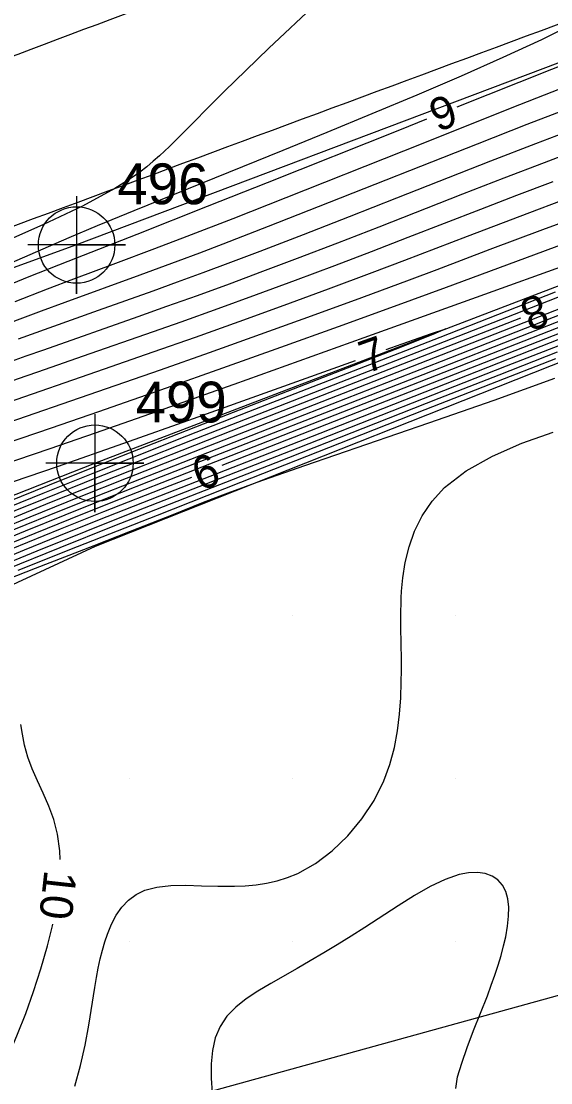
# Model space of a CAD drawing. Extents: x 2602990 to 2605851, y 618069 to 619180.
# Drawn here: x 2603243.4 to 2603275.8, y 618321.3 to 618386.4 of the extents above; entities that cross this region are included whole.
import ezdxf

# ---------------------------------------------------------------- set-up
doc = ezdxf.new("R2010")
doc.units = 0
for name, color, linetype in [('DTM Contours Major', 7, 'Continuous'), ('DTM Contours Minor', 7, 'Continuous'), ('DTM Contours Minor Text', 7, 'Continuous'), ('Exist DTM Breakline', 7, 'Continuous'), ('Exist DTM Breakline Cogo Number', 7, 'Continuous'), ('Exist DTM Breakline Cogo Point CELL', 7, 'Continuous'), ('Exist DTM Crownline', 7, 'Continuous'), ('Exist DTM Drainline', 7, 'Continuous'), ('Exist DTM Drainline Cogo Number', 7, 'Continuous'), ('Exist DTM Drainline Cogo Point CELL', 7, 'Continuous'), ('Exist DTM QL2 LIDAR Elevation Point', 7, 'Continuous'), ('Exist Roads EOP', 7, 'Continuous'), ('PH Exist DTM Breakline', 7, 'Continuous'), ('PH Exist DTM Obscure Area', 7, 'Continuous')]:
    doc.layers.add(name, color=color, linetype=linetype)

# ---------------------------------------------------------------- blocks, each defined once
blk = doc.blocks.new('EXIST DTM BREAKLINE COGO POINT')
at = {"layer": 'Exist DTM Breakline Cogo Point CELL'}
blk.add_lwpolyline([(0, 0.06), (0, -0.06), (0, 0), (0.06, 0), (-0.06, 0)], dxfattribs=at)
blk.add_circle((0, 0), 0.0469, dxfattribs=at)
blk = doc.blocks.new('EXIST DTM DRAINLINE COGO POINT')
at = {"layer": 'Exist DTM Drainline Cogo Point CELL'}
blk.add_lwpolyline([(0, 0.06), (0, -0.06), (0, 0), (0.06, 0), (-0.06, 0)], dxfattribs=at)
blk.add_circle((0, 0), 0.0469, dxfattribs=at)

msp = doc.modelspace()

# ---------------------------------------------------------------- linework, layer by layer
at = {"layer": 'DTM Contours Major'}
for points in [[(2603232.042, 618350.596), (2603232.796, 618350.941), (2603234.02, 618351.488), (2603235.249, 618352.027), (2603236.484, 618352.559), (2603237.724, 618353.086), (2603240.316, 618354.172), (2603243.023, 618355.288), (2603245.739, 618356.391), (2603248.557, 618357.518), (2603251.681, 618358.75), (2603259.068, 618361.639), (2603269.134, 618365.569), (2603283.544, 618371.218), (2603285.941, 618372.151), (2603288.321, 618373.072), (2603290.658, 618373.969), (2603292.932, 618374.831), (2603294.547, 618375.436), (2603297.726, 618376.612), (2603305.437, 618379.437), (2603325.265, 618386.744)], [(2603275.946, 618376.566), (2603273.731, 618375.723), (2603271.513, 618374.867), (2603267.062, 618373.138), (2603264.824, 618372.273), (2603262.574, 618371.415), (2603260.163, 618370.511), (2603257.768, 618369.629), (2603255.419, 618368.776), (2603253.148, 618367.963), (2603250.987, 618367.198), (2603247.571, 618366.005), (2603244.375, 618364.896), (2603243.115, 618364.454), (2603241.834, 618363.997), (2603240.512, 618363.517), (2603239.134, 618363.003), (2603237.103, 618362.225), (2603234.953, 618361.384), (2603230.386, 618359.589), (2603228.019, 618358.671), (2603225.675, 618357.78)]]:
    msp.add_lwpolyline(points, dxfattribs=at)
at = {"layer": 'DTM Contours Minor'}
for points in [[(2603324.577, 618403.317), (2603322.127, 618402.396), (2603318.389, 618401.013), (2603317.044, 618400.508), (2603315.774, 618400.025), (2603314.571, 618399.561), (2603313.423, 618399.112), (2603312.32, 618398.675), (2603310.615, 618397.984), (2603308.924, 618397.283), (2603307.17, 618396.544), (2603304.397, 618395.361), (2603295.959, 618391.738), (2603291.729, 618389.935), (2603289.635, 618389.049), (2603287.605, 618388.196), (2603285.68, 618387.395), (2603284.13, 618386.757), (2603282.641, 618386.15), (2603279.672, 618384.956), (2603270.072, 618381.131)], [(2603230.899, 618351.261), (2603232.523, 618351.981), (2603234.797, 618352.972), (2603236.387, 618353.653), (2603237.889, 618354.288), (2603239.501, 618354.962), (2603241.21, 618355.669), (2603243.003, 618356.405), (2603244.868, 618357.163), (2603248.004, 618358.424), (2603250.561, 618359.439), (2603253.762, 618360.7), (2603260.83, 618363.464), (2603273.604, 618368.443), (2603287.265, 618373.796), (2603290.393, 618375.014), (2603293.467, 618376.203), (2603297.403, 618377.709), (2603300.32, 618378.809), (2603305.717, 618380.822), (2603313.054, 618383.538), (2603329.838, 618389.732)], [(2603261.504, 618387.535), (2603258.551, 618384.748), (2603257.131, 618383.391), (2603255.828, 618382.119), (2603255.057, 618381.347), (2603253.687, 618379.95), (2603253.059, 618379.318), (2603252.451, 618378.723), (2603251.848, 618378.162), (2603251.461, 618377.82), (2603251.06, 618377.486), (2603250.634, 618377.156), (2603250.174, 618376.824), (2603249.668, 618376.489), (2603249.106, 618376.144), (2603247.123, 618375.074), (2603244.699, 618373.921), (2603241.954, 618372.712)], [(2603277.305, 618386.282), (2603275.256, 618385.263), (2603272.901, 618384.172), (2603270.327, 618383.036), (2603267.62, 618381.879), (2603264.866, 618380.727), (2603262.092, 618379.582), (2603259.4, 618378.482), (2603250.263, 618374.78), (2603248.017, 618373.853), (2603246.286, 618373.122), (2603243.894, 618372.089), (2603240.538, 618370.626)], [(2603255.688, 618359.187), (2603263.04, 618362.061), (2603279.19, 618368.395), (2603282.779, 618369.794), (2603284.501, 618370.46), (2603286.202, 618371.112), (2603287.902, 618371.757), (2603289.622, 618372.402), (2603291.762, 618373.195), (2603293.952, 618373.996), (2603302.985, 618377.265), (2603307.387, 618378.871), (2603325.442, 618385.504)], [(2603238.982, 618351.734), (2603239.621, 618352.003), (2603241.64, 618352.839), (2603244.34, 618353.944), (2603247.34, 618355.154), (2603250.445, 618356.384), (2603260.34, 618360.258), (2603273.119, 618365.279), (2603276.379, 618366.555), (2603280.836, 618368.288), (2603283.497, 618369.311), (2603286.09, 618370.291), (2603287.416, 618370.786), (2603289.927, 618371.711), (2603292.552, 618372.665), (2603297.95, 618374.609), (2603303.224, 618376.505), (2603308.514, 618378.427), (2603321.931, 618383.339), (2603327.334, 618385.332)], [(2603279.496, 618383.471), (2603273.91, 618381.27), (2603266.799, 618378.447), (2603259.591, 618375.584), (2603256.333, 618374.299), (2603253.51, 618373.199), (2603251.536, 618372.444), (2603249.137, 618371.547), (2603246.582, 618370.596), (2603244.96, 618369.98), (2603242.977, 618369.207)], [(2603278.586, 618381.696), (2603274.359, 618380.063), (2603271.308, 618378.867), (2603261.577, 618375.019), (2603258.513, 618373.816), (2603255.727, 618372.737), (2603254.294, 618372.191), (2603252.976, 618371.696), (2603250.634, 618370.833), (2603246.036, 618369.17), (2603244.593, 618368.636), (2603242.953, 618368.014), (2603242.033, 618367.658), (2603239.439, 618366.634), (2603229.996, 618362.845), (2603226.732, 618361.55), (2603223.628, 618360.343), (2603221.906, 618359.689), (2603220.263, 618359.076), (2603218.677, 618358.493), (2603217.297, 618357.991)], [(2603268.214, 618380.39), (2603266.551, 618379.727), (2603258.435, 618376.492), (2603254.775, 618375.038), (2603250.453, 618373.333), (2603246.232, 618371.683), (2603243.838, 618370.73), (2603240.938, 618369.559), (2603233.675, 618366.612), (2603229.728, 618365.015), (2603225.849, 618363.457), (2603222.246, 618362.028), (2603219.869, 618361.1), (2603215.419, 618359.389), (2603207.46, 618356.337), (2603204.769, 618355.31), (2603202.133, 618354.311), (2603197.891, 618352.72), (2603196.251, 618352.098), (2603194.676, 618351.476), (2603193.162, 618350.839), (2603191.704, 618350.169), (2603190.299, 618349.451), (2603188.941, 618348.673)], [(2603276.602, 618379.55), (2603274.89, 618378.895), (2603272.142, 618377.829), (2603266.365, 618375.557), (2603263.467, 618374.417), (2603260.654, 618373.316), (2603257.989, 618372.289), (2603256.195, 618371.61), (2603254.508, 618370.981), (2603252.924, 618370.4), (2603251.439, 618369.863), (2603248.081, 618368.667), (2603245.055, 618367.591), (2603243.19, 618366.908)], [(2603277.384, 618378.473), (2603275.422, 618377.731), (2603272.943, 618376.779), (2603270.41, 618375.793), (2603265.29, 618373.787), (2603262.757, 618372.802), (2603260.277, 618371.85), (2603258.158, 618371.052), (2603256.112, 618370.295), (2603254.149, 618369.579), (2603252.282, 618368.908), (2603250.519, 618368.281), (2603244.728, 618366.249), (2603243.647, 618365.864), (2603242.526, 618365.458)], [(2603276.469, 618375.402), (2603274.521, 618374.668), (2603270.705, 618373.207), (2603266.856, 618371.731), (2603264.867, 618370.977), (2603262.193, 618369.981), (2603259.456, 618368.977), (2603256.715, 618367.986), (2603254.025, 618367.024), (2603251.444, 618366.112), (2603247.982, 618364.905), (2603242.563, 618363.034)], [(2603276.988, 618374.236), (2603275.32, 618373.616), (2603272.1, 618372.402), (2603268.852, 618371.173), (2603267.148, 618370.534), (2603264.223, 618369.452), (2603261.148, 618368.329), (2603258.009, 618367.197), (2603254.889, 618366.084), (2603251.875, 618365.019), (2603248.044, 618363.683), (2603242.004, 618361.609)], [(2603277.464, 618373.057), (2603274.778, 618372.07), (2603269.423, 618370.086), (2603266.226, 618368.914), (2603262.799, 618367.671), (2603259.254, 618366.395), (2603255.701, 618365.127), (2603252.251, 618363.907), (2603248.097, 618362.458), (2603245.196, 618361.462), (2603241.459, 618360.187)], [(2603276.657, 618371.416), (2603271.775, 618369.658), (2603264.366, 618366.987), (2603260.389, 618365.56), (2603256.4, 618364.136), (2603252.525, 618362.764), (2603247.893, 618361.145), (2603245.13, 618360.195), (2603239.035, 618358.121)], [(2603240.938, 618354.805), (2603243.907, 618356.024), (2603246.945, 618357.251), (2603249.812, 618358.391), (2603253.938, 618360.013), (2603271.955, 618367.048), (2603283.767, 618371.679)], [(2603241.137, 618354.141), (2603243.629, 618355.163), (2603246.066, 618356.149), (2603248.768, 618357.226), (2603251.969, 618358.486), (2603268, 618364.751), (2603281.124, 618369.898)], [(2603242.64, 618356.632), (2603244.704, 618357.472), (2603247.878, 618358.748), (2603249.988, 618359.588), (2603253.512, 618360.979), (2603257.314, 618362.47), (2603269.043, 618367.042), (2603276.129, 618369.808)], [(2603241.955, 618354.103), (2603244.225, 618355.031), (2603246.397, 618355.907), (2603248.986, 618356.937), (2603253.987, 618358.899), (2603264.4, 618362.967), (2603281.079, 618369.507)], [(2603241.8, 618355.537), (2603243.44, 618356.209), (2603245.122, 618356.892), (2603248.168, 618358.114), (2603250.998, 618359.235), (2603257.009, 618361.593), (2603272.791, 618367.75), (2603274, 618368.224)], [(2603265.745, 618366.285), (2603266.032, 618366.387), (2603268.458, 618367.242), (2603269.401, 618367.544), (2603268.59, 618367.192), (2603266.291, 618366.283), (2603254.511, 618361.701), (2603249.508, 618359.736), (2603247.981, 618359.13), (2603245.089, 618357.969), (2603242.511, 618356.919)], [(2603240.86, 618352.88), (2603243.57, 618353.999), (2603246.222, 618355.079), (2603248.64, 618356.047), (2603251.863, 618357.316), (2603261.685, 618361.158), (2603276.497, 618366.971)], [(2603242.416, 618352.8), (2603245.76, 618354.151), (2603249.004, 618355.441), (2603258.998, 618359.36), (2603268.99, 618363.294), (2603272.659, 618364.733), (2603276.239, 618366.132)], [(2603242.896, 618358.193), (2603245.582, 618359.117), (2603249.653, 618360.539), (2603253.935, 618362.058), (2603263.862, 618365.611)], [(2603243.185, 618352.763), (2603246.816, 618354.207), (2603251.718, 618356.13), (2603256.833, 618358.139), (2603264.249, 618361.068), (2603268.125, 618362.595), (2603272.149, 618364.172), (2603276.15, 618365.728)], [(2603241.458, 618351.802), (2603244.245, 618352.882), (2603247.832, 618354.267), (2603250.072, 618355.14), (2603252.687, 618356.175), (2603254.438, 618356.873), (2603255.557, 618357.306), (2603256.21, 618357.551), (2603256.959, 618357.826), (2603257.827, 618358.138), (2603260.757, 618359.163), (2603268.348, 618361.78), (2603272.358, 618363.184), (2603276.074, 618364.523)], [(2603246.647, 618321.116), (2603247.007, 618322.38), (2603247.287, 618323.635), (2603247.51, 618324.863), (2603247.875, 618327.169), (2603247.979, 618327.78), (2603248.09, 618328.364), (2603248.21, 618328.923), (2603248.342, 618329.455), (2603248.487, 618329.961), (2603248.65, 618330.442), (2603248.902, 618331.053), (2603249.198, 618331.61), (2603249.543, 618332.104), (2603249.943, 618332.527), (2603250.407, 618332.873), (2603250.939, 618333.132), (2603251.691, 618333.329), (2603252.536, 618333.419), (2603253.455, 618333.435), (2603254.426, 618333.41), (2603255.428, 618333.379), (2603256.441, 618333.374), (2603257.104, 618333.402), (2603257.761, 618333.463), (2603258.413, 618333.562), (2603259.058, 618333.707), (2603259.695, 618333.904), (2603260.324, 618334.16), (2603261.407, 618334.762), (2603262.438, 618335.539), (2603263.395, 618336.462), (2603264.254, 618337.504), (2603264.994, 618338.636), (2603265.592, 618339.83), (2603265.967, 618340.845), (2603266.244, 618341.873), (2603266.438, 618342.903), (2603266.564, 618343.926), (2603266.636, 618344.931), (2603266.668, 618345.907), (2603266.675, 618346.602), (2603266.673, 618347.278), (2603266.645, 618349.231), (2603266.642, 618349.866), (2603266.644, 618350.263), (2603266.651, 618350.661), (2603266.666, 618351.059), (2603266.688, 618351.461), (2603266.72, 618351.865), (2603266.763, 618352.275), (2603266.912, 618353.227), (2603267.146, 618354.191), (2603267.484, 618355.151), (2603267.946, 618356.087), (2603268.55, 618356.982), (2603269.315, 618357.818), (2603270.647, 618358.849), (2603272.25, 618359.75), (2603274.052, 618360.535), (2603275.982, 618361.222)], [(2603242.766, 618354.058), (2603245.778, 618355.282), (2603248.43, 618356.342), (2603252.488, 618357.936), (2603253.825, 618358.459)], [(2603245.75, 618335.011), (2603245.738, 618335.548), (2603245.598, 618336.575), (2603245.367, 618337.459), (2603245.063, 618338.294), (2603244.718, 618339.086), (2603244.367, 618339.844), (2603244.041, 618340.573), (2603243.774, 618341.283), (2603243.577, 618342.017), (2603243.449, 618342.701), (2603243.354, 618343.3)], [(2603270, 618320.984), (2603270.122, 618321.689), (2603270.368, 618322.538), (2603270.705, 618323.495), (2603271.101, 618324.525), (2603271.525, 618325.594), (2603271.943, 618326.666), (2603272.181, 618327.307), (2603272.403, 618327.934), (2603272.606, 618328.546), (2603272.786, 618329.142), (2603272.941, 618329.719), (2603273.068, 618330.276), (2603273.182, 618330.927), (2603273.244, 618331.537), (2603273.249, 618332.102), (2603273.192, 618332.612), (2603273.068, 618333.063), (2603272.869, 618333.446), (2603272.588, 618333.761), (2603272.232, 618333.997), (2603271.81, 618334.15), (2603271.328, 618334.218), (2603270.794, 618334.199), (2603270.216, 618334.09), (2603269.358, 618333.794), (2603268.441, 618333.356), (2603267.478, 618332.808), (2603266.481, 618332.185), (2603264.428, 618330.847), (2603263.584, 618330.312), (2603262.743, 618329.793), (2603261.91, 618329.292), (2603261.088, 618328.807), (2603260.281, 618328.341), (2603258.663, 618327.422), (2603257.878, 618326.956), (2603257.156, 618326.476), (2603256.515, 618325.966), (2603255.975, 618325.406), (2603255.553, 618324.781), (2603255.264, 618324.084), (2603255.09, 618323.317), (2603255.011, 618322.492), (2603255.009, 618321.62), (2603255.064, 618320.713)], [(2603241.669, 618321.107), (2603241.832, 618321.413), (2603241.997, 618321.739), (2603242.165, 618322.085), (2603242.645, 618323.133), (2603243.143, 618324.309), (2603243.643, 618325.584), (2603244.127, 618326.93), (2603244.579, 618328.318), (2603244.983, 618329.719), (2603245.286, 618330.946), (2603245.306, 618331.047)]]:
    msp.add_lwpolyline(points, dxfattribs=at)
at = {"layer": 'Exist DTM Breakline'}
msp.add_lwpolyline([(2603537.954, 618480.779), (2603486.109, 618461.906), (2603428.704, 618440.722), (2603369.241, 618418.295), (2603303.922, 618394.289), (2603246.763, 618372.687), (2603198.271, 618355.074)], dxfattribs=at)
at = {"layer": 'Exist DTM Crownline'}
msp.add_spline([(2603233.488, 618380.754), (2603285.185, 618400.095), (2603335.457, 618418.629), (2603390.812, 618439.069), (2603440.087, 618457.325), (2603493.996, 618477.231), (2603542.655, 618495.301), (2603600.808, 618516.867), (2603653.659, 618536.362), (2603706.222, 618555.742), (2603764.811, 618577.593), (2603823.52, 618599.847), (2603878.564, 618620.56), (2603937.951, 618643.078), (2603997.369, 618665.789), (2604036.209, 618680.665), (2604055.311, 618688.017)], degree=3, dxfattribs=at)
at = {"layer": 'Exist DTM Drainline'}
msp.add_lwpolyline([(2603204.098, 618342.063), (2603247.886, 618359.31), (2603300.002, 618379.256), (2603348.063, 618397.511), (2603388.725, 618412.554), (2603432.793, 618429.056), (2603474.09, 618444.074), (2603510.151, 618459.891), (2603545.952, 618474.924)], dxfattribs=at)
at = {"layer": 'Exist DTM QL2 LIDAR Elevation Point'}
for p, q in [((2603260, 618350), (2603260, 618350)), ((2603270, 618350), (2603270, 618350)), ((2603250, 618340), (2603250, 618340)), ((2603260, 618340), (2603260, 618340)), ((2603270, 618340), (2603270, 618340)), ((2603250, 618330), (2603250, 618330)), ((2603260, 618330), (2603260, 618330)), ((2603270, 618330), (2603270, 618330))]:
    msp.add_line(p, q, dxfattribs=at)
at = {"layer": 'Exist Roads EOP'}
msp.add_spline([(2604034.633, 618668.486), (2603984.89, 618650.123), (2603936.767, 618631.654), (2603888.195, 618613.335), (2603837.766, 618594.258), (2603782.918, 618573.705), (2603731.939, 618554.39), (2603671.126, 618532.171), (2603621.822, 618514.106), (2603561.545, 618491.877), (2603506.421, 618471.293), (2603452.163, 618451.33), (2603398.364, 618431.316), (2603341.431, 618410.355), (2603281.65, 618388.199), (2603223.033, 618366.475), (2603185.717, 618352.612)], degree=3, dxfattribs=at)
at = {"layer": 'PH Exist DTM Breakline'}
msp.add_lwpolyline([(2603546.278, 618467.89), (2603526.855, 618460.306), (2603507.213, 618451.651), (2603485.725, 618442.619), (2603466.383, 618433.876), (2603454.696, 618429.386), (2603442.234, 618424.385), (2603428.822, 618418.102), (2603416.965, 618413.956), (2603393.207, 618405.535), (2603378.639, 618399.772), (2603357.505, 618392.883), (2603332.502, 618384.211), (2603305.954, 618375.46), (2603282.242, 618367.811), (2603247.909, 618354.209), (2603229.683, 618345.761), (2603219.668, 618341.177), (2603212.41, 618339.282), (2603206.143, 618338.068)], dxfattribs=at)
at = {"layer": 'PH Exist DTM Obscure Area'}
msp.add_lwpolyline([(2603434.389, 618378.195), (2603391.714, 618364.121), (2603301.286, 618333.579), (2603234.869, 618315.243)], dxfattribs=at)

# ---------------------------------------------------------------- block references
at = {"layer": 'Exist DTM Breakline Cogo Point CELL', "xscale": 50, "yscale": 50}
msp.add_blockref('EXIST DTM BREAKLINE COGO POINT', (2603246.763, 618372.687), dxfattribs=at)
at = {"layer": 'Exist DTM Drainline Cogo Point CELL', "xscale": 50, "yscale": 50}
msp.add_blockref('EXIST DTM DRAINLINE COGO POINT', (2603247.886, 618359.31), dxfattribs=at)
msp.add_blockref('EXIST DTM DRAINLINE COGO POINT', (2603247.886, 618359.31), dxfattribs=at)

# ---------------------------------------------------------------- texts
at = {"layer": 'DTM Contours Minor Text'}
for s, rotation, p in [('9', 21.72765, (2603268.906, 618379.589)), ('8', 201.40509, (2603275.175, 618369.758)), ('7', 19.69157, (2603264.525, 618364.786)), ('9', 201.34873, (2603255.001, 618359.993)), ('10', 263.59786, (2603244.796, 618334.42))]:
    msp.add_text(s, height=2, rotation=rotation, dxfattribs=at).set_placement(p)
at = {"layer": 'Exist DTM Breakline Cogo Number'}
msp.add_text('496', height=2.5, dxfattribs=at).set_placement((2603249.263, 618375.187))
at = {"layer": 'Exist DTM Drainline Cogo Number'}
msp.add_text('499', height=2.5, dxfattribs=at).set_placement((2603250.386, 618361.81))

doc.saveas('drawing.dxf')
